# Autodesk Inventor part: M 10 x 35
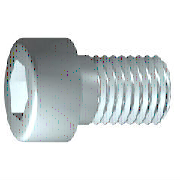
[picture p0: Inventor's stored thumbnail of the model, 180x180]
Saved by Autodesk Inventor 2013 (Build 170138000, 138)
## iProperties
IsCustomPart: 0
Created: 2009-02
Part Number: M 10 x 35
Material: 강, 연강
Description: 6각머리 태핑 나사
Document SubType Name: Modeling
Standard: KS B 1003
Designer: KYOUNG IL JANG
Standards Organization: KS
Language: ko-KR
Size Designation: M 10 x 35
Categories: <MemberInstance><Categories><Category DisplayName="조임쇠" InternalName="e4da775c-781d-43d5-af7c-5136215cf5a6" Mnemonic="FSTN"><Category DisplayName="볼트" InternalN
Density: 7.86 g/cm^3
Mass: 34.5961 g
Surface Area: 21.1658 cm^2
Volume: 4.40154 cm^3
Author: KYOUNG IL JANG
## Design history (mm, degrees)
sketch "스케치1"
  geometry: L1 (-2.333, 0)-(35, 0); L2 (35, 0)-(35, 5); L3 (35, 5)-(3.75, 5); L4 (3.75, 5)-(2.83, 5); L5 (2.83, 5)-(0, 5); L6 (0, 5)-(0, 8); L7 (0, 8)-(-10, 8); L8 (-10, 8)-(-10, 4.619); L9 (-10, 4.619)-(-5, 4.619); L10 (-5, 4.619)-(-2.333, 0); L11 (-19, 0)-(44, 0) reference; L12 (0, -1.6)-(0, 9.6) reference; L13 (3.75, 5)-(0, 5)
  constraints: 22 end point, 6 parallel, 2 collinear, 2 perpendicular, 1 horizontal, 1 point on line
  dimensions: "d1" = 31.25 distance from line of L3.end L2 (= GEL); "d2" = 0.92028 distance of L4.end L3.end (computed from GAL); "d3" = 10 distance between parallel lines of L8 L6 (= KOH); "d4" = 5 distance of L8.end L9.end (= INTI); "d5" = 60 deg angle of L10 L1; "d6" = 10 diameter of L3 L1 (= GD); "d7" = 10 diameter of L5 L1 (= BDM); "d8" = 9.2376 diameter of L9 L1 (= 1.1547 x SW); "d9" = 16 diameter of L7 L1 (= KOD); "d26" = 35 distance between parallel lines of L12 L2 (= NLG)
revolve "본체" sketch "스케치1" stored, may be unused: angle "d10" = 90 deg
sketch "스케치2"
  geometry: L1 (0, -11.2)-(0, 11.2) reference; L2 (-11.2, 0)-(11.2, 0) reference; L3 (4.619, 0)-(2.309, -4); L4 (2.309, -4)-(-2.309, -4); L5 (-2.309, -4)-(-4.619, 0); L6 (-4.619, 0)-(-2.309, 4); L7 (-2.309, 4)-(2.309, 4); L8 (2.309, 4)-(4.619, 0); 2 further points
  constraints: 12 end point, 1 coincident, 1 horizontal alignment, 1 point on line, 12 other
extrude "슬롯" join sketch "스케치2" stored distance "d11" = 10; taper "d12" = 0 deg
workplane "Work Plane1"
fillet "Fillet2" dims "d30" = 0.1 (= R)
body "Solid1"
fillet "모깎기1" dims "d17" = 1 (= RR)
feature "스레드" dims "d13" = 31.25 (= GEL), "d14" = 0
chamfer "모따기1" distance "d15" = 0.92018 (= -0.5 x SPD + 0.5 x GD); stored, may be unused: second distance "d16" = 0.92018 (= GUL), angle "d27" = 45 deg
other parameters: "GD" = 10 (= NND) [user parameter; used in 2 equation terms], "NLG" = 35 [user parameter; used in 1 equation term], "GEL" = 31.25 [user parameter; used in 2 equation terms], "KOD" = 16 [user parameter; used in 1 equation term], "KOH" = 10 [user parameter; used in 1 equation term], "INTI" = 5 [user parameter; used in 1 equation term], "GAL" = 0.92018 (= 0.61345 x PTC) [user parameter; used in 1 equation term], "GUL" = 0.92018 (= 0.61345 x PTC) [user parameter; used in 1 equation term], "BDM" = 10 (= NND) [user parameter; used in 1 equation term], "SW" = 8 [user parameter; used in 2 equation terms], "RR" = 1 [user parameter; used in 1 equation term], "SPD" = 8.15965 (= NND - 1.2269 x PTC) [user parameter; used in 1 equation term], "d19" = 0, "d28" = 0, "d29" = 0, "R" = 0.1 [user parameter; used in 1 equation term], "PHH" = 0.4 [user parameter], "GD1" = 8.15965 (= THREADDIA - 1.2269 x PTC) [user parameter], "FAWI" = 45 deg [user parameter], "TPU" = 6.66667 (computed from PTC) [user parameter], "PTC" = 1.5 [user parameter; used in 5 equation terms], "TOA" = 30 deg [user parameter], "E0" = 9.24 (= 1.155 x SW) [user parameter]
